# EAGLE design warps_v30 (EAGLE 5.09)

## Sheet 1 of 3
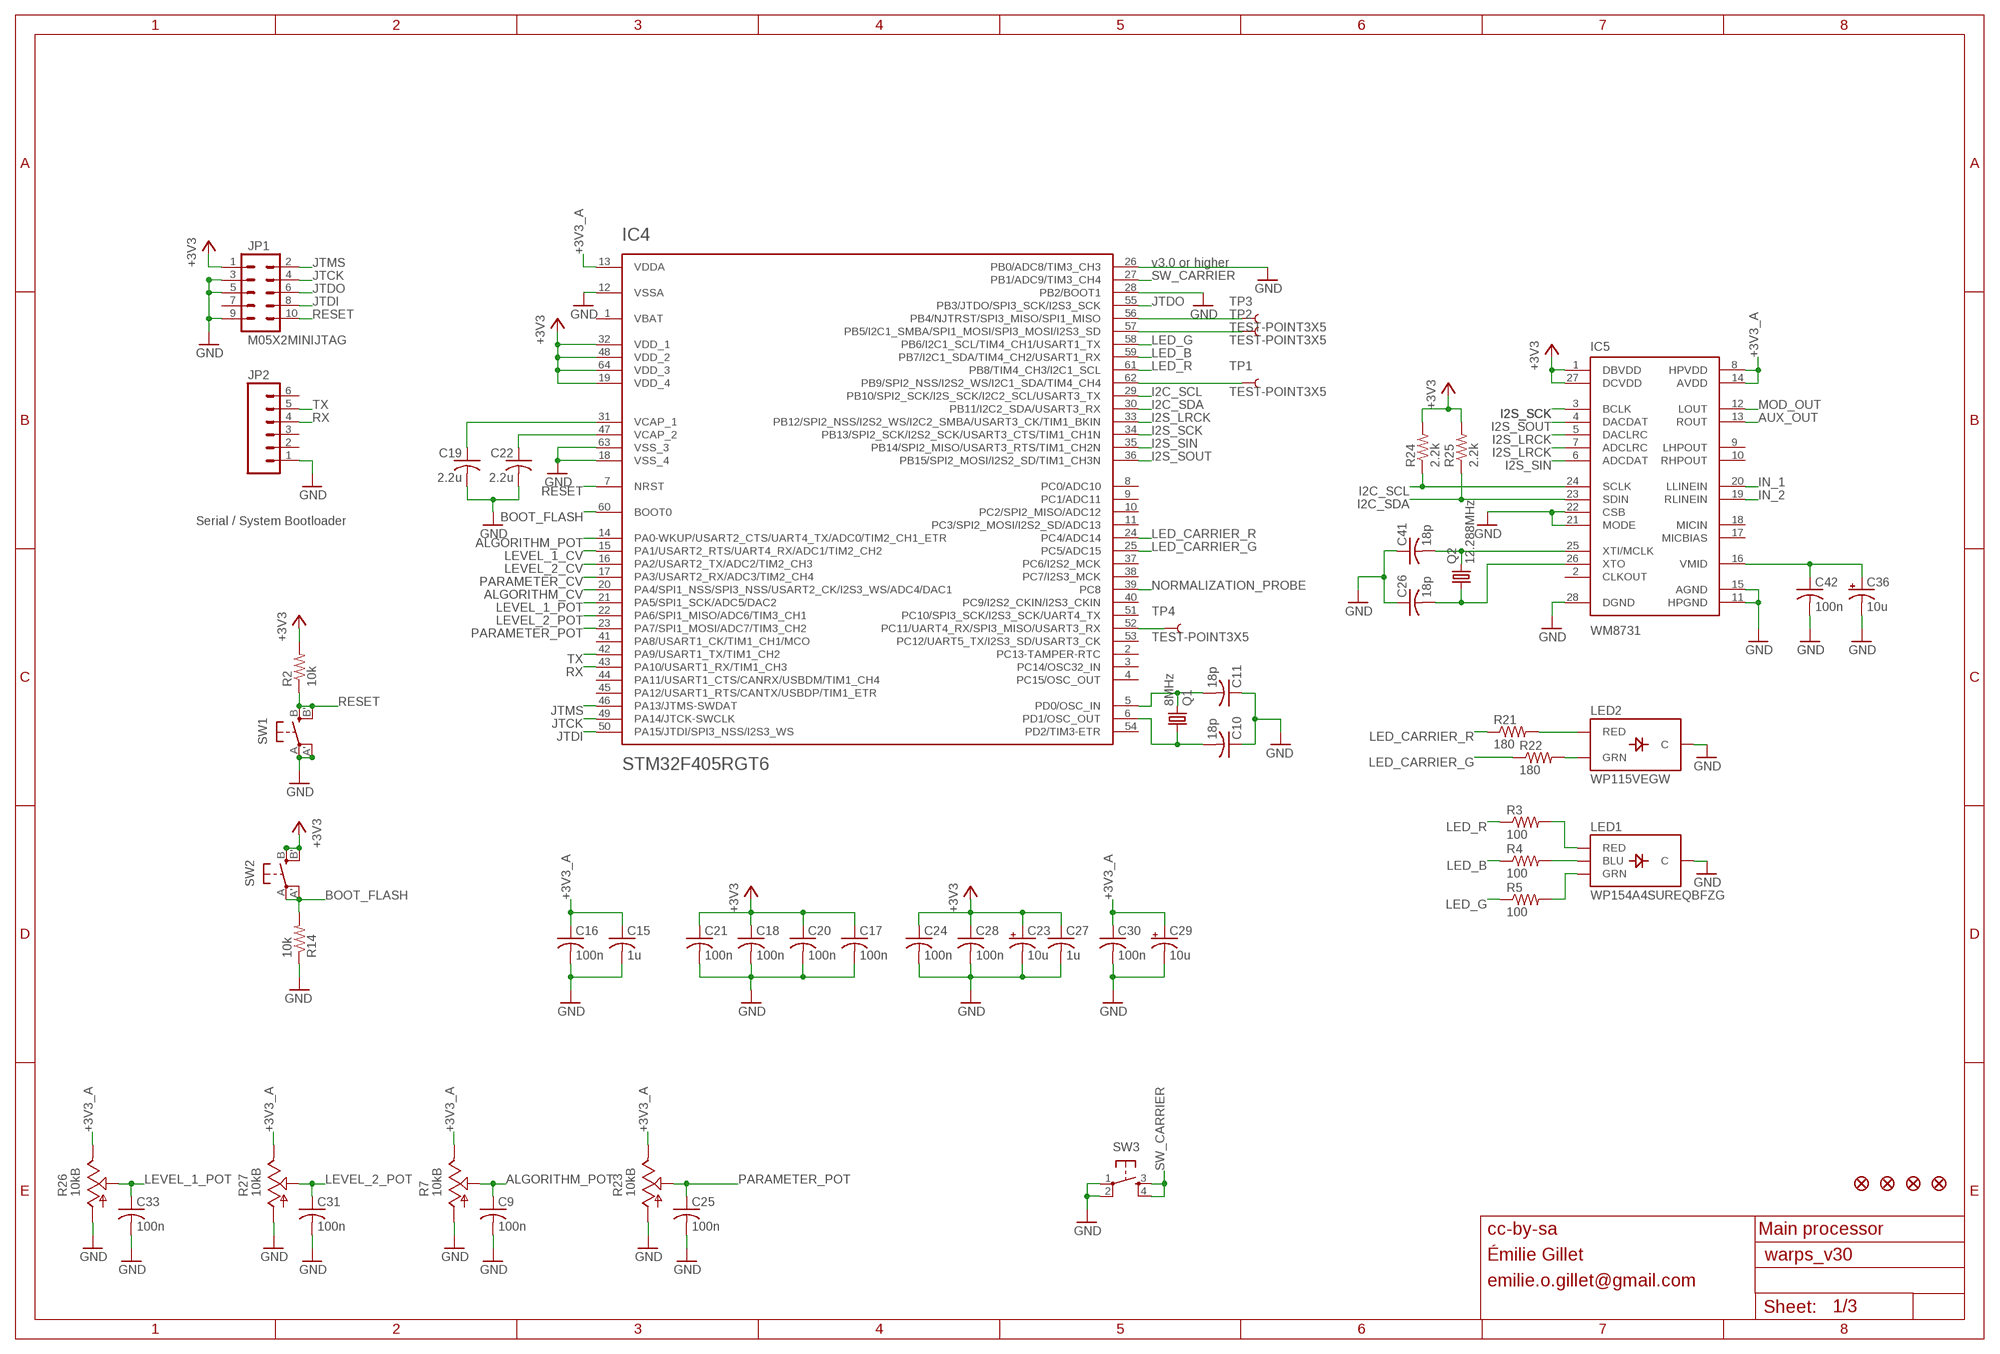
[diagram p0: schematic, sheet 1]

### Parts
C9  100n  C-USC0603  [C0603]
C10  18p  C-USC0603  [C0603]
C11  18p  C-USC0603  [C0603]
C15  1u  C-USC0603  [C0603]
C16  100n  C-USC0603  [C0603]
C17  100n  C-USC0603  [C0603]
C18  100n  C-USC0603  [C0603]
C19  2.2u  C-USC0805  [C0805]
C20  100n  C-USC0603  [C0603]
C21  100n  C-USC0603  [C0603]
C22  2.2u  C-USC0805  [C0805]
C23  10u  CPOL-USA  [PANASONIC_A]
C24  100n  C-USC0603  [C0603]
C25  100n  C-USC0603  [C0603]
C26  18p  C-USC0603  [C0603]
C27  1u  C-USC0603  [C0603]
C28  100n  C-USC0603  [C0603]
C29  10u  CPOL-USA  [PANASONIC_A]
C30  100n  C-USC0603  [C0603]
C31  100n  C-USC0603  [C0603]
C33  100n  C-USC0603  [C0603]
C36  10u  CPOL-USA  [PANASONIC_A]
C41  18p  C-USC0603  [C0603]
C42  100n  C-USC0603  [C0603]
F1  FIDUCIAL1X2  [FIDUCIAL-1X2]
F2  FIDUCIAL1X2  [FIDUCIAL-1X2]
F3  FIDUCIAL1X2  [FIDUCIAL-1X2]
F4  FIDUCIAL1X2  [FIDUCIAL-1X2]
IC4  STM32F405RGT6  STM32F20X  [TQFP-10X10-64]
IC5  WM8731  [SSOP28]
JP1  M05X2MINIJTAG  [2X5-1.27]
JP2  M06SIP  [1X06]
LED1  WP154A4SUREQBFZG  LED-TRICOLOR-THROUGHHOLE  [LED-TRICOLOR-THROUGHHOLE]
LED2  WP115VEGW  LED-BICOLOR-THROUGHHOLE  [LED-BICOLOR-THROUGHHOLE]
Q1  8MHz  CRYSTALHC49UP  [HC49UP]
Q2  12.288MHz  CRYSTALHC49UP  [HC49UP]
R2  10k  R-US_R0603  [R0603]
R3  100  R-US_R0603  [R0603]
R4  100  R-US_R0603  [R0603]
R5  100  R-US_R0603  [R0603]
R7  10kB  POT_USVERTICAL_PS  [ALPS_POT_VERTICAL_PS]
R14  10k  R-US_R0603  [R0603]
R21  180  R-US_R0603  [R0603]
R22  180  R-US_R0603  [R0603]
R23  10kB  POT_USVERTICAL_PS  [ALPS_POT_VERTICAL_PS]
R24  2.2k  R-US_R0603  [R0603]
R25  2.2k  R-US_R0603  [R0603]
R26  10kB  POT_USVERTICAL  [ALPS_POT_VERTICAL]
R27  10kB  POT_USVERTICAL  [ALPS_POT_VERTICAL]
SW1  EVQQ2  [EVQ-Q2]
SW2  EVQQ2  [EVQ-Q2]
SW3  TAC_SWITCHPTH  [TACTILE-PTH]
TP1  TEST-POINT3X5  [PAD.03X.05]
TP2  TEST-POINT3X5  [PAD.03X.05]
TP3  TEST-POINT3X5  [PAD.03X.05]
TP4  TEST-POINT3X5  [PAD.03X.05]

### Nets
+3V3: C17.1 C18.1 C20.1 C21.1 C23.+ C24.1 C27.1 C28.1 IC4.19(VDD_4) IC4.32(VDD_1) IC4.48(VDD_2) IC4.64(VDD_3) IC5.1(DBVDD) IC5.27(DCVDD) JP1.1 R2.2 R24.2 R25.2 SW2.B'(S1) SW2.B(S) ; also sheet 2,3
+3V3_A: C15.1 C16.1 C29.+ C30.1 IC4.13(VDDA) IC5.8(HPVDD) IC5.14(AVDD) R7.P$1(E) R23.P$1(E) R26.P$1(E) R27.P$1(E) ; also sheet 2,3
ALGORITHM_CV: IC4.20(PA4/SPI1_NSS/SPI3_NSS/USART2_CK/I2S3_WS/ADC4/DAC1) ; also sheet 2
ALGORITHM_POT: C9.1 IC4.14(PA0-WKUP/USART2_CTS/UART4_TX/ADC0/TIM2_CH1_ETR) R7.P$2(S)
AUX_OUT: IC5.13(ROUT) ; also sheet 2
BOOT_FLASH: IC4.60(BOOT0) R14.2 SW2.A'(P1) SW2.A(P)
GND: C9.2 C10.1 C11.1 C15.2 C16.2 C17.2 C18.2 C19.2 C20.2 C21.2 C22.2 C23.- C24.2 C25.2 C26.1 C27.2 C28.2 C29.- C30.2 C31.2 C33.2 C36.- C41.1 C42.2 IC4.12(VSSA) IC4.18(VSS_4) IC4.26(PB0/ADC8/TIM3_CH3) IC4.28(PB2/BOOT1) IC4.63(VSS_3) IC5.11(HPGND) IC5.15(AGND) IC5.21(MODE) IC5.22(CSB) IC5.28(DGND) JP1.3 JP1.5 JP1.9 JP2.1 LED1.GND(C) LED2.2(C) R7.P$3(A) R14.1 R23.P$3(A) R26.P$3(A) R27.P$3(A) SW1.A'(P1) SW1.A(P) SW3.1 SW3.2 ; also sheet 2,3
I2C_SCL: IC4.29(PB10/SPI2_SCK/I2S_SCK/I2C2_SCL/USART3_TX) IC5.24(SCLK) R24.1
I2C_SDA: IC4.30(PB11/I2C2_SDA/USART3_RX) IC5.23(SDIN) R25.1
I2S_LRCK: IC4.33(PB12/SPI2_NSS/I2S2_WS/I2C2_SMBA/USART3_CK/TIM1_BKIN) IC5.5(DACLRC) IC5.7(ADCLRC)
I2S_SCK: IC4.34(PB13/SPI2_SCK/I2S2_SCK/USART3_CTS/TIM1_CH1N) IC5.3(BCLK)
I2S_SIN: IC4.35(PB14/SPI2_MISO/USART3_RTS/TIM1_CH2N) IC5.6(ADCDAT)
I2S_SOUT: IC4.36(PB15/SPI2_MOSI/I2S2_SD/TIM1_CH3N) IC5.4(DACDAT)
IN_1: IC5.20(LLINEIN) ; also sheet 2
IN_2: IC5.19(RLINEIN) ; also sheet 2
JTCK: IC4.49(PA14/JTCK-SWCLK) JP1.4
JTDI: IC4.50(PA15/JTDI/SPI3_NSS/I2S3_WS) JP1.8
JTDO: IC4.55(PB3/JTDO/SPI3_SCK/I2S3_SCK) JP1.6
JTMS: IC4.46(PA13/JTMS-SWDAT) JP1.2
LED_B: IC4.59(PB7/I2C1_SDA/TIM4_CH2/USART1_RX) R4.1
LED_CARRIER_G: IC4.25(PC5/ADC15) R22.1
LED_CARRIER_R: IC4.24(PC4/ADC14) R21.1
LED_G: IC4.58(PB6/I2C1_SCL/TIM4_CH1/USART1_TX) R5.1
LED_R: IC4.61(PB8/TIM4_CH3/I2C1_SCL) R3.1
LEVEL_1_CV: IC4.15(PA1/USART2_RTS/UART4_RX/ADC1/TIM2_CH2) ; also sheet 2
LEVEL_1_POT: C33.1 IC4.21(PA5/SPI1_SCK/ADC5/DAC2) R26.P$2(S)
LEVEL_2_CV: IC4.16(PA2/USART2_TX/ADC2/TIM2_CH3) ; also sheet 2
LEVEL_2_POT: C31.1 IC4.22(PA6/SPI1_MISO/ADC6/TIM3_CH1) R27.P$2(S)
MOD_OUT: IC5.12(LOUT) ; also sheet 2
N$3: LED2.3(RED) R21.2
N$7: C11.2 IC4.5(PD0/OSC_IN) Q1.2
N$8: C10.2 IC4.6(PD1/OSC_OUT) Q1.1
N$13: C22.1 IC4.47(VCAP_2)
N$14: LED2.1(GRN) R22.2
N$17: C36.+ C42.1 IC5.16(VMID)
N$19: C19.1 IC4.31(VCAP_1)
N$24: IC4.56(PB4/NJTRST/SPI3_MISO/SPI1_MISO) TP3.P$1
N$26: IC4.57(PB5/I2C1_SMBA/SPI1_MOSI/SPI3_MOSI/I2S3_SD) TP2.P$1
N$27: IC4.52(PC11/UART4_RX/SPI3_MISO/USART3_RX) TP4.P$1
N$30: IC4.62(PB9/SPI2_NSS/I2S2_WS/I2C1_SDA/TIM4_CH4) TP1.P$1
N$35: LED1.RED R3.2
N$36: LED1.BLU R4.2
N$37: LED1.GRN R5.2
N$40: C41.2 IC5.25(XTI/MCLK) Q2.2
N$41: C26.2 IC5.26(XTO) Q2.1
NORMALIZATION_PROBE: IC4.39(PC8) ; also sheet 2
PARAMETER_CV: IC4.17(PA3/USART2_RX/ADC3/TIM2_CH4) ; also sheet 2
PARAMETER_POT: C25.1 IC4.23(PA7/SPI1_MOSI/ADC7/TIM3_CH2) R23.P$2(S)
RESET: IC4.7(NRST) JP1.10 R2.1 SW1.B'(S1) SW1.B(S)
RX: IC4.43(PA10/USART1_RX/TIM1_CH3) JP2.4
SW_CARRIER: IC4.27(PB1/ADC9/TIM3_CH4) SW3.3 SW3.4
TX: IC4.42(PA9/USART1_TX/TIM1_CH2) JP2.5
Unconnected: IC4.2(PC13-TAMPER-RTC) IC4.3(PC14/OSC32_IN) IC4.4(PC15/OSC_OUT) IC4.8(PC0/ADC10) IC4.9(PC1/ADC11) IC4.10(PC2/SPI2_MISO/ADC12) IC4.11(PC3/SPI2_MOSI/I2S2_SD/ADC13) IC4.37(PC6/I2S2_MCK) IC4.38(PC7/I2S3_MCK) IC4.40(PC9/I2S2_CKIN/I2S3_CKIN) IC4.41(PA8/USART1_CK/TIM1_CH1/MCO) IC4.44(PA11/USART1_CTS/CANRX/USBDM/TIM1_CH4) IC4.45(PA12/USART1_RTS/CANTX/USBDP/TIM1_ETR) IC4.51(PC10/SPI3_SCK/I2S3_SCK/UART4_TX) IC4.53(PC12/UART5_TX/I2S3_SD/USART3_CK) IC4.54(PD2/TIM3-ETR) IC5.2(CLKOUT) IC5.9(LHPOUT) IC5.10(RHPOUT) IC5.17(MICBIAS) IC5.18(MICIN) JP1.7 JP2.2 JP2.3 JP2.6

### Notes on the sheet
- v3.0 or higher
- Serial / System Bootloader
- cc-by-sa | Main processor
- Émilie Gillet
- emilie.o.gillet@gmail.com

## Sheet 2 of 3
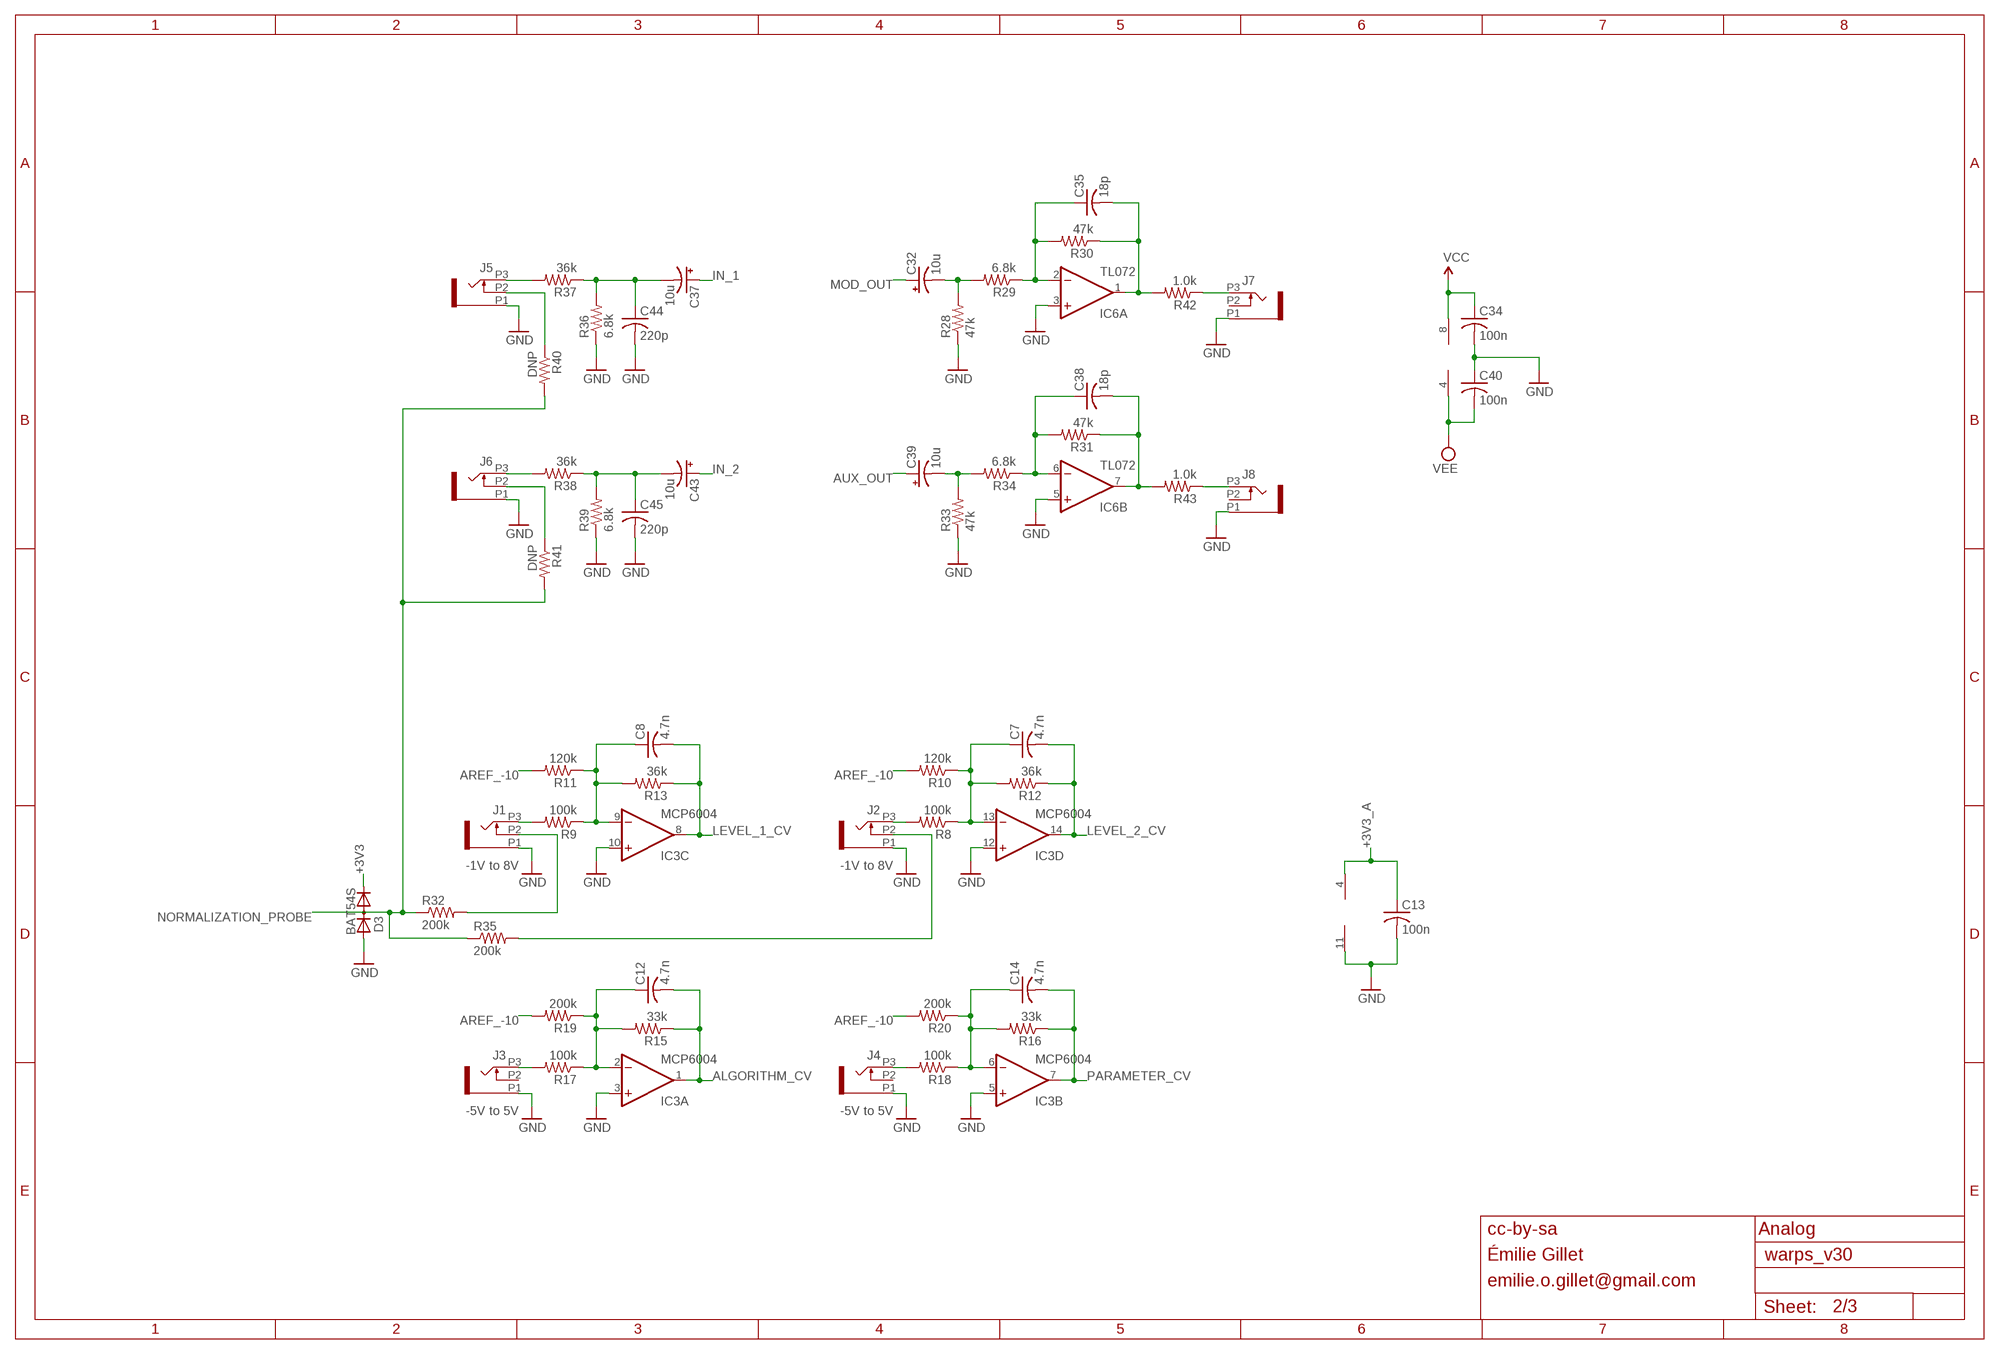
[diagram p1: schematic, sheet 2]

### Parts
C7  4.7n  C-USC0603  [C0603]
C8  4.7n  C-USC0603  [C0603]
C12  4.7n  C-USC0603  [C0603]
C13  100n  C-USC0603  [C0603]
C14  4.7n  C-USC0603  [C0603]
C32  10u  CPOL-USA  [PANASONIC_A]
C34  100n  C-USC0603  [C0603]
C35  18p  C-USC0603  [C0603]
C37  10u  CPOL-USA  [PANASONIC_A]
C38  18p  C-USC0603  [C0603]
C39  10u  CPOL-USA  [PANASONIC_A]
C40  100n  C-USC0603  [C0603]
C43  10u  CPOL-USA  [PANASONIC_A]
C44  220p  C-USC0603  [C0603]
C45  220p  C-USC0603  [C0603]
D3  BAT54S  DIODE_2CACA-SOT23  [SOT23]
IC3  MCP6004  TL074D  [SO14]
IC6  TL072  TL072D  [SO08]
J1  PJ301_THONKICONN6  [WQP_PJ_301M6]
J2  PJ301_THONKICONN6  [WQP_PJ_301M6]
J3  PJ301_THONKICONN6  [WQP_PJ_301M6]
J4  PJ301_THONKICONN6  [WQP_PJ_301M6]
J5  PJ301_THONKICONN6  [WQP_PJ_301M6]
J6  PJ301_THONKICONN6  [WQP_PJ_301M6]
J7  PJ301_THONKICONN6  [WQP_PJ_301M6]
J8  PJ301_THONKICONN6  [WQP_PJ_301M6]
R8  100k  R-US_R0603  [R0603]
R9  100k  R-US_R0603  [R0603]
R10  120k  R-US_R0603  [R0603]
R11  120k  R-US_R0603  [R0603]
R12  36k  R-US_R0603  [R0603]
R13  36k  R-US_R0603  [R0603]
R15  33k  R-US_R0603  [R0603]
R16  33k  R-US_R0603  [R0603]
R17  100k  R-US_R0603  [R0603]
R18  100k  R-US_R0603  [R0603]
R19  200k  R-US_R0603  [R0603]
R20  200k  R-US_R0603  [R0603]
R28  47k  R-US_R0603  [R0603]
R29  6.8k  R-US_R0603  [R0603]
R30  47k  R-US_R0603  [R0603]
R31  47k  R-US_R0603  [R0603]
R32  200k  R-US_R0603  [R0603]
R33  47k  R-US_R0603  [R0603]
R34  6.8k  R-US_R0603  [R0603]
R35  200k  R-US_R0603  [R0603]
R36  6.8k  R-US_R0603  [R0603]
R37  36k  R-US_R0603  [R0603]
R38  36k  R-US_R0603  [R0603]
R39  6.8k  R-US_R0603  [R0603]
R40  DNP  R-US_R0603  [R0603]
R41  DNP  R-US_R0603  [R0603]
R42  1.0k  R-US_R0603  [R0603]
R43  1.0k  R-US_R0603  [R0603]

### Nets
+3V3: D3.2(C) ; also sheet 1,3
+3V3_A: C13.1 IC3.4(P:V+) ; also sheet 1,3
ALGORITHM_CV: C12.2 IC3.1(A:OUT) R15.1 ; also sheet 1
AREF_-10: R10.2 R11.2 R19.2 R20.2 ; also sheet 3
AUX_OUT: C39.+ ; also sheet 1
GND: C13.2 C34.2 C40.1 C44.2 C45.2 D3.1(A) IC3.3(A:+IN) IC3.5(B:+IN) IC3.10(C:+IN) IC3.11(P:V-) IC3.12(D:+IN) IC6.3(A:+IN) IC6.5(B:+IN) J1.P1 J2.P1 J3.P1 J4.P1 J5.P1 J6.P1 J7.P1 J8.P1 R28.1 R33.1 R36.1 R39.1 ; also sheet 1,3
IN_1: C37.+ ; also sheet 1
IN_2: C43.+ ; also sheet 1
LEVEL_1_CV: C8.2 IC3.8(C:OUT) R13.1 ; also sheet 1
LEVEL_2_CV: C7.2 IC3.14(D:OUT) R12.1 ; also sheet 1
MOD_OUT: C32.+ ; also sheet 1
N$1: J1.P3 R9.2
N$2: C8.1 IC3.9(C:-IN) R9.1 R11.1 R13.2
N$4: J2.P3 R8.2
N$5: C7.1 IC3.13(D:-IN) R8.1 R10.1 R12.2
N$6: J4.P3 R18.2
N$9: J1.P2 R32.2
N$10: J3.P3 R17.2
N$11: C12.1 IC3.2(A:-IN) R15.2 R17.1 R19.1
N$12: J2.P2 R35.2
N$15: C14.1 IC3.6(B:-IN) R16.2 R18.1 R20.1
N$18: C37.- C44.1 R36.2 R37.1
N$20: J6.P3 R38.2
N$21: J5.P3 R37.2
N$22: C43.- C45.1 R38.1 R39.2
N$23: C39.- R33.2 R34.2
N$25: C38.1 IC6.6(B:-IN) R31.2 R34.1
N$28: C38.2 IC6.7(B:OUT) R31.1 R43.2
N$29: J8.P3 R43.1
N$31: C32.- R28.2 R29.2
N$32: C35.1 IC6.2(A:-IN) R29.1 R30.2
N$33: C35.2 IC6.1(A:OUT) R30.1 R42.2
N$34: J7.P3 R42.1
N$38: J6.P2 R41.1
N$39: J5.P2 R40.1
NORMALIZATION_PROBE: D3.3(AC) R32.1 R35.1 R40.2 R41.2 ; also sheet 1
PARAMETER_CV: C14.2 IC3.7(B:OUT) R16.1 ; also sheet 1
VCC: C34.1 IC6.8(P:V+) ; also sheet 3
VEE: C40.2 IC6.4(P:V-) ; also sheet 3
Unconnected: J3.P2 J4.P2 J7.P2 J8.P2

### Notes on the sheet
- -1V to 8V | -1V to 8V
- -5V to 5V | -5V to 5V
- cc-by-sa | Analog
- Émilie Gillet
- emilie.o.gillet@gmail.com

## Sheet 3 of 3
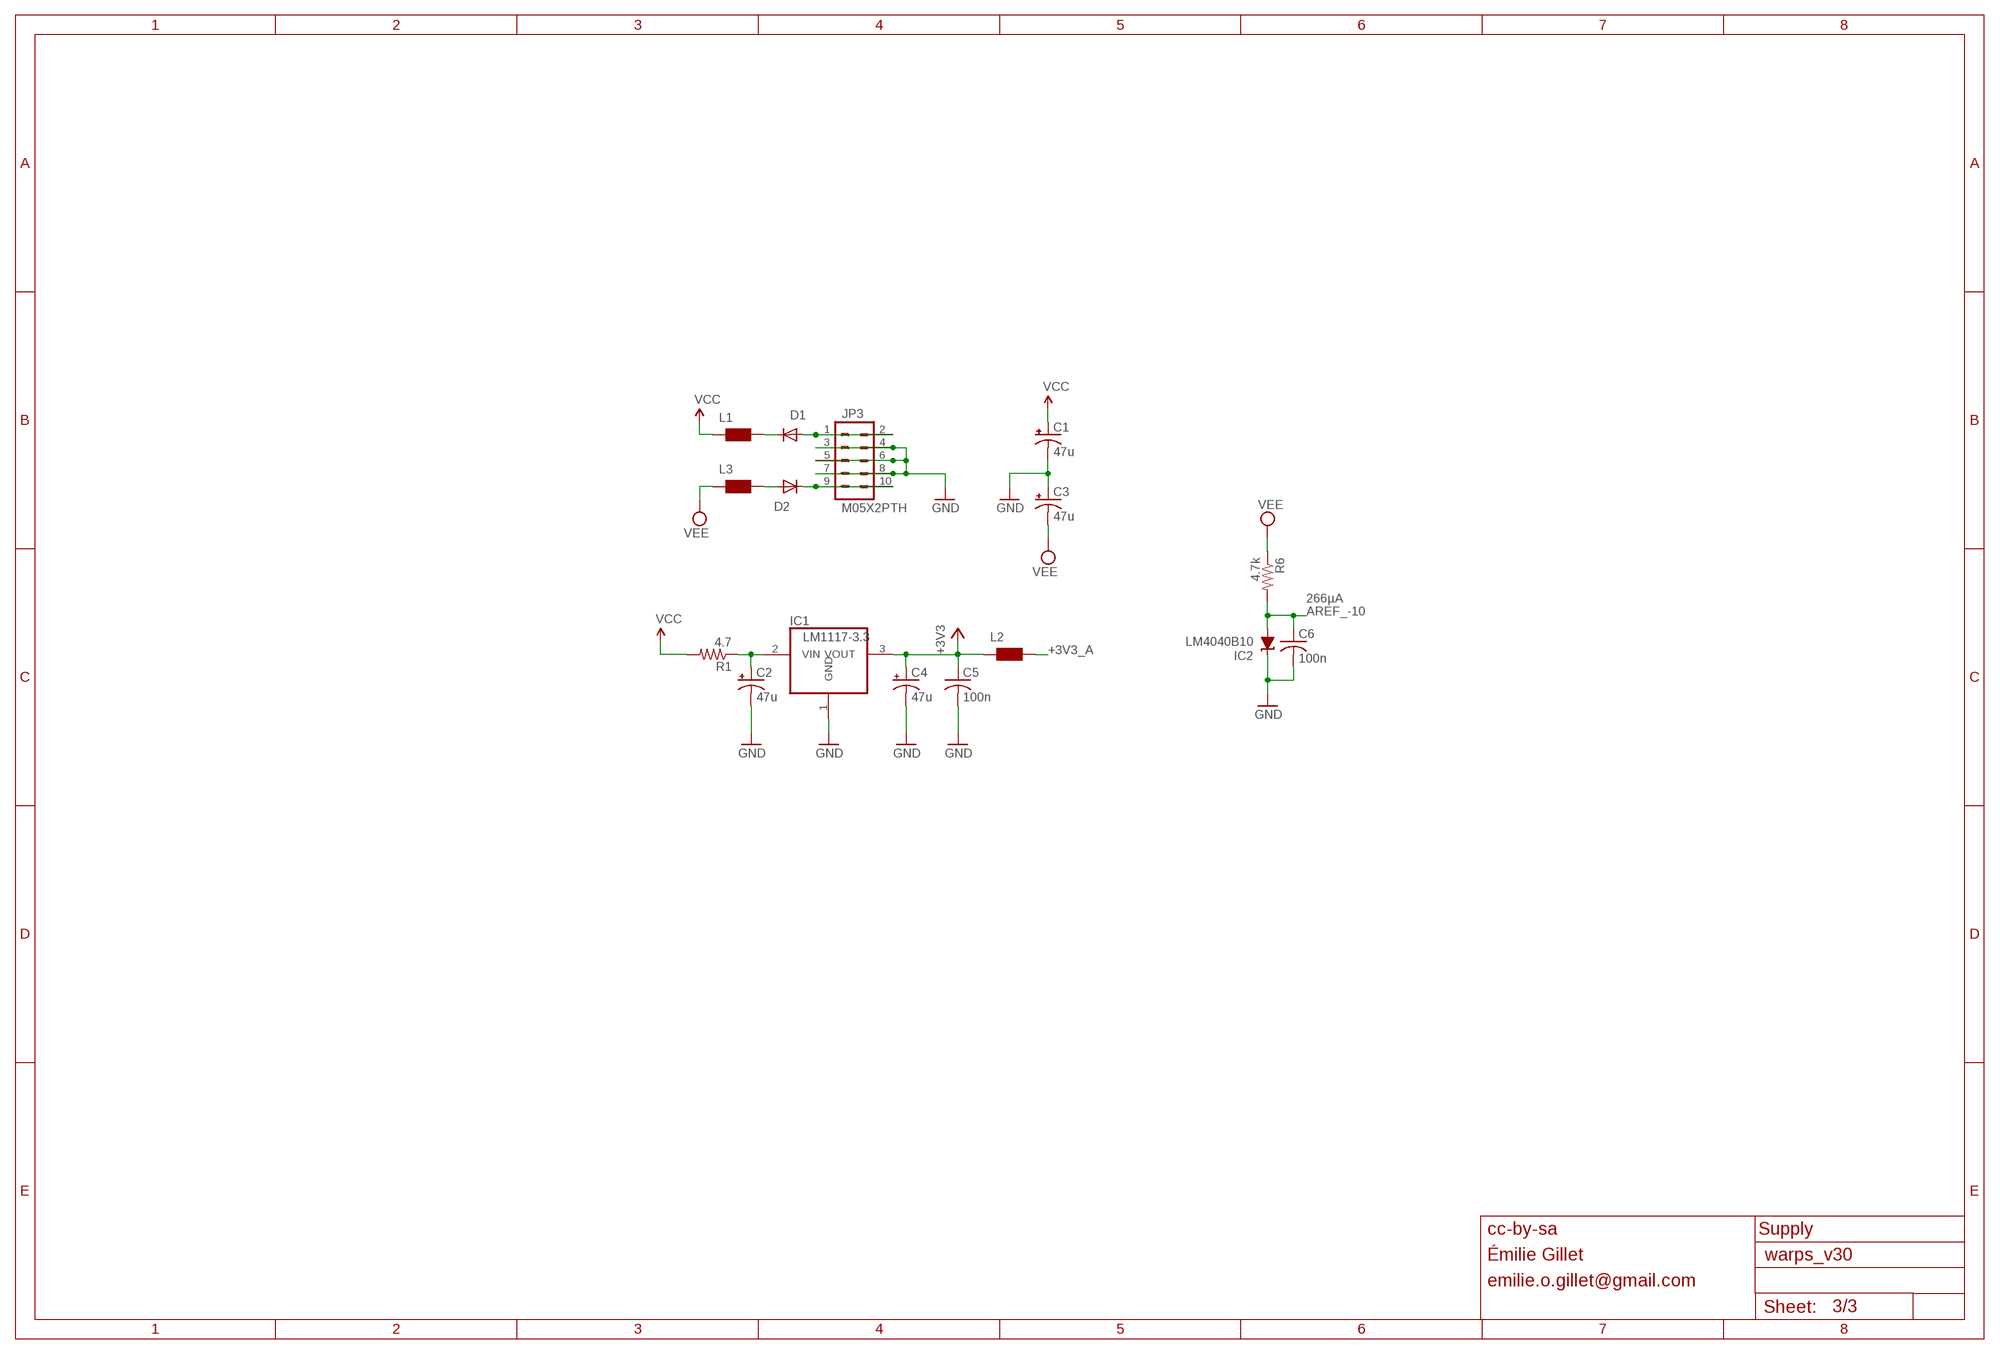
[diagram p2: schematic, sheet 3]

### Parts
C1  47u  CPOL-USD  [PANASONIC_D]
C2  47u  CPOL-USD  [PANASONIC_D]
C3  47u  CPOL-USD  [PANASONIC_D]
C4  47u  CPOL-USD  [PANASONIC_D]
C5  100n  C-USC0603  [C0603]
C6  100n  C-USC0603  [C0603]
D1  1N5819HW  DIODE-SOD123  [SOD123]
D2  1N5819HW  DIODE-SOD123  [SOD123]
IC1  LM1117-3.3  REG1117T  [TO252]
IC2  LM4040B10  LM4041B12DBZ  [DBZ_R-PDSO-G3]
JP3  M05X2PTH  [AVR_ICSP]
L1  WE-CBF_0603  [0603]
L2  WE-CBF_0603  [0603]
L3  WE-CBF_0603  [0603]
R1  4.7  R-US_R1206  [R1206]
R6  4.7k  R-US_R0603  [R0603]

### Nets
+3V3: C4.+ C5.1 IC1.3(VOUT) L2.1 ; also sheet 1,2
+3V3_A: L2.2 ; also sheet 1,2
AREF_-10: C6.1 IC2.2(A) R6.2 ; also sheet 2
GND: C1.- C2.- C3.+ C4.- C5.2 C6.2 IC1.1(GND) IC2.1(C) JP3.3 JP3.4 JP3.5 JP3.6 JP3.7 JP3.8 ; also sheet 1,2
N$16: C2.+ IC1.2(VIN) R1.1
N$42: D1.C L1.2
N$43: D2.A L3.2
N$56: D1.A JP3.1 JP3.2
N$64: D2.C JP3.9 JP3.10
VCC: C1.+ L1.1 R1.2 ; also sheet 2
VEE: C3.- L3.1 R6.1 ; also sheet 2

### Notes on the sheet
- 266µA
- cc-by-sa | Supply
- Émilie Gillet
- emilie.o.gillet@gmail.com

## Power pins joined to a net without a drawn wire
VBAT: IC4.1(VBAT)

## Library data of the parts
C1-C4 C23 C29 C32 C36 C37 C39 C43 = rcl:CPOL-US: POLARIZED CAPACITOR, American symbol
C5-C22 C24-C28 C30 C31 C33-C35 C38 C40-C42 C44 C45 = rcl:C-US: CAPACITOR, American symbol
D1 D2 = diode:DIODE-: DIODE
D3 = diode:DIODE_2CACA-: 2 Diodes - Cathode-Anode|Cathode-Anode
F1-F4 = SparkFun:FIDUCIAL: Fiducial Alignment Points
IC1 = og-vreg:REG1117: 800mA and 1A Low Dropout (LDO) Positive Regulator 1.8V, 2.5V, 2.85V, 3.3V, 5V, and Adj
IC2 = texas:LM4041: PRECISION MICROPOWER SHUNT VOLTAGE REFERENCE
IC3 = gm-ics:TL074: OP AMP
IC4 = og-stm32f2:STM32F20X
IC5 = og-dac:WM8731
IC6 = og-linear:TL072: OP AMP
J1-J8 = og-pj301:PJ301_THONKICONN
JP1 JP3 = og-header:M05X2: Header 5x2 Standard 10-pin dual row 0.1" header. Commonly used with AVR-ISP. Use with Spark Fun Electronics SKU: PRT-00778
JP2 = SparkFun:M06: Header 6 Standard 6-pin 0.1" header. Use with straight break away headers (SKU : PRT-00116), right angle break away headers (PRT-00553), swiss pins (PRT-00743), machine pins (PRT-00117), and female headers (PRT-00115). Molex polarized connector foot print use with SKU : PRT-08094 with associated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
L1-L3 = wuerth-elektronik:WE-CBF: SMD EMI Suppression Ferrite Beads
LED1 = og-leds:LED-TRICOLOR-THROUGHHOLE
LED2 = og-leds:LED-BICOLOR-THROUGHHOLE
Q1 Q2 = crystal:CRYSTAL: CRYSTAL
R1-R6 R8-R22 R24 R25 R28-R43 = rcl:R-US_: RESISTOR, American symbol
R7 R23 R26 R27 = og-pots:POT_US
SW1 SW2 = adafruit:EVQQ2: SMT 6mm switch, EVQQ2 series http://www.ladyada.net/library/eagle
SW3 = SparkFun:TAC_SWITCH: Momentary Switch Button commonly used for reset or general input. Spark Fun Electronics SKU : COM-00097
TP1-TP4 = SparkFun:TEST-POINT

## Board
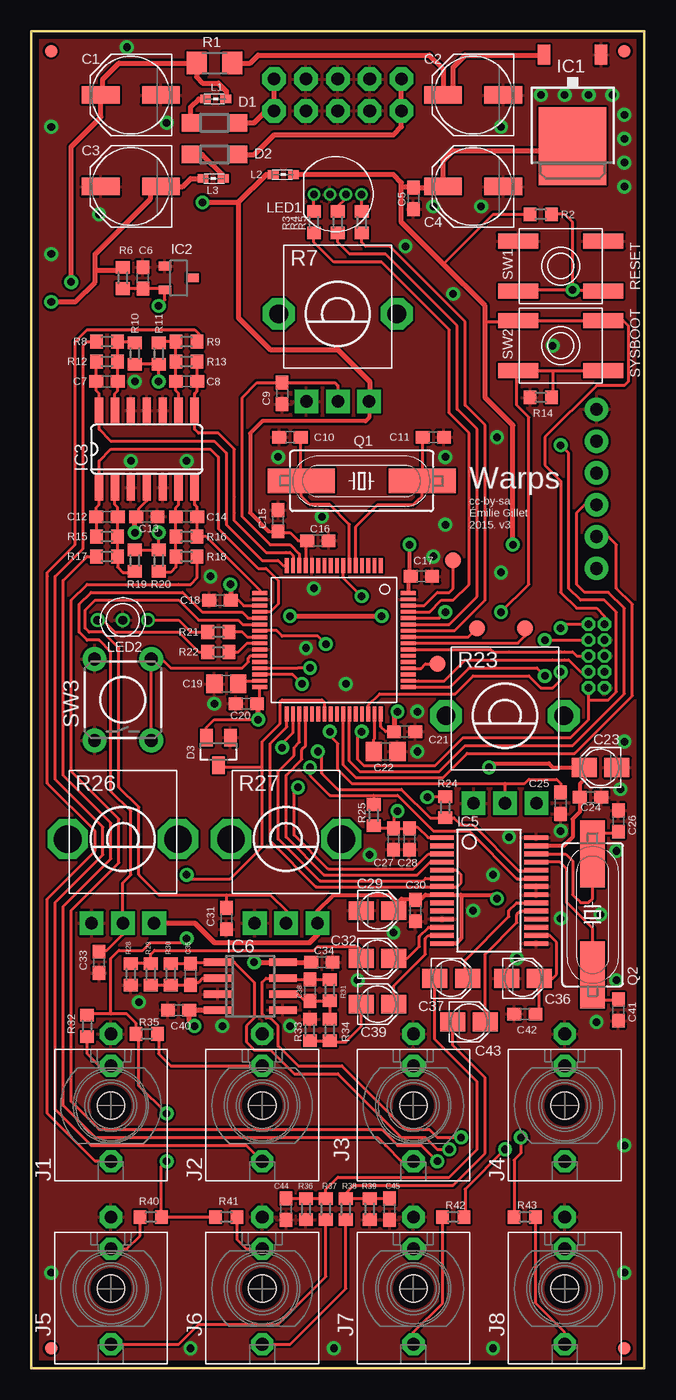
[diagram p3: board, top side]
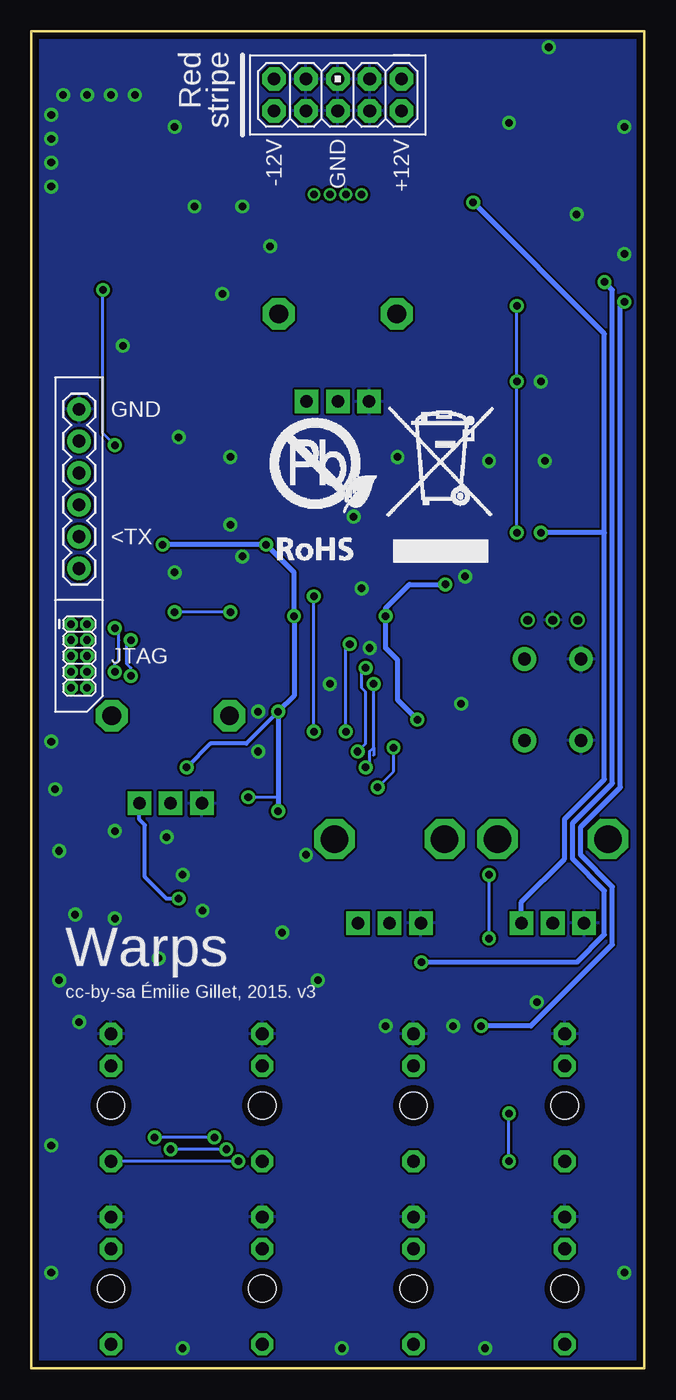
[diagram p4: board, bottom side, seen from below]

Size 48.9 x 106.68 mm. Coordinates in mm from the lower left corner, seen from the top.
Outline: 0,0 48.9,0 48.9,106.68 0,106.68 0,0
Copper layers (1*16): Top 0.035mm / dielectric 1.5mm / Bottom 0.035mm
Design rules "PCBCart-Standard-Fine": minimum track width 8mil, minimum drill 0.4mm, track to track 7mil, track to pad 7mil, pad to pad 7mil, via to via 7mil, smd to smd 7mil, copper to edge 20mil, drill to drill 8mil, minimum pad ring 8mil, minimum via ring 10mil, stop-mask expansion 3mil, vias tented up to drill 25mil, thermal gap 8mil

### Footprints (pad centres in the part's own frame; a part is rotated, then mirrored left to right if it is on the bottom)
PANASONIC_D = smd 3 x 1.4: + 2.4,0; - -2.4,0
C0603 = smd 1.1 x 1: 1 -0.85,0; 2 0.85,0
C0805 = smd 1.3 x 1.5: 1 -0.95,0; 2 0.95,0
PANASONIC_A = smd 2 x 1.5: + 1.3,0; - -1.3,0
SOD123 = smd 1.4 x 1.4: A 1.9,0; C -1.9,0
SOT23 = smd 1 x 1.4: 1 -0.95,-1.1; 2 0.95,-1.1; 3 0,1.1
FIDUCIAL-1X2 = smd 1 x 1: 1 0,0
TO252 = smd 1 x 1.6: 1 -2.28,-4.8; 2 2.28,-4.8 | smd 5.4 x 6.2: 3 0,2.5
DBZ_R-PDSO-G3 = smd 0.7 x 1: 1 -0.95,-1.1; 2 0.95,-1.1; 3 0,1.1
SO14 = smd 0.66 x 2.032: 1 -3.81,-3.073; 2 -2.54,-3.073; 3 -1.27,-3.073; 4 0,-3.073; 5 1.27,-3.073; 6 2.54,-3.073; 7 3.81,-3.073; 8 3.81,3.073; 9 2.54,3.073; 10 1.27,3.073; 11 0,3.073; 12 -1.27,3.073; 13 -2.54,3.073; 14 -3.81,3.073
TQFP-10X10-64 = smd 1.2 x 0.3: 1 -5.936,3.75; 2 -5.936,3.25; 3 -5.936,2.75; 4 -5.936,2.25; 5 -5.936,1.75; 6 -5.936,1.25; 7 -5.936,0.75; 8 -5.936,0.25; 9 -5.936,-0.25; 10 -5.936,-0.75; 11 -5.936,-1.25; 12 -5.936,-1.75; 13 -5.936,-2.25; 14 -5.936,-2.75; 15 -5.936,-3.25; 16 -5.936,-3.75; 33 5.886,-3.75; 34 5.886,-3.25; 35 5.886,-2.75; 36 5.886,-2.25; 37 5.886,-1.75; 38 5.886,-1.25; 39 5.886,-0.75; 40 5.886,-0.25; 41 5.886,0.25; 42 5.886,0.75; 43 5.886,1.25; 44 5.886,1.75; 45 5.886,2.25; 46 5.886,2.75; 47 5.886,3.25; 48 5.886,3.75 | smd 0.3 x 1.2: 17 -3.75,-5.911; 18 -3.25,-5.911; 19 -2.75,-5.911; 20 -2.25,-5.911; 21 -1.75,-5.911; 22 -1.25,-5.911; 23 -0.75,-5.911; 24 -0.25,-5.911; 25 0.25,-5.911; 26 0.75,-5.911; 27 1.25,-5.911; 28 1.75,-5.911; 29 2.25,-5.911; 30 2.75,-5.911; 31 3.25,-5.911; 32 3.75,-5.911; 49 3.75,5.936; 50 3.25,5.936; 51 2.75,5.936; 52 2.25,5.936; 53 1.75,5.936; 54 1.25,5.936; 55 0.75,5.936; 56 0.25,5.936; 57 -0.25,5.936; 58 -0.75,5.936; 59 -1.25,5.936; 60 -1.75,5.936; 61 -2.25,5.936; 62 -2.75,5.936; 63 -3.25,5.936; 64 -3.75,5.936
SSOP28 = smd 0.381 x 1.905: 1 -4.55,-3.752; 2 -3.9,-3.752; 3 -3.25,-3.752; 4 -2.6,-3.752; 5 -1.95,-3.752; 6 -1.3,-3.752; 7 -0.65,-3.752; 8 0,-3.752; 9 0.65,-3.752; 10 1.3,-3.752; 11 1.95,-3.752; 12 2.6,-3.752; 13 3.25,-3.752; 14 3.9,-3.752; 15 3.9,3.752; 16 3.25,3.752; 17 2.6,3.752; 18 1.95,3.752; 19 1.3,3.752; 20 0.65,3.752; 21 0,3.752; 22 -0.65,3.752; 23 -1.3,3.752; 24 -1.95,3.752; 25 -2.6,3.752; 26 -3.25,3.752; 27 -3.9,3.752; 28 -4.55,3.752
SO08 = smd 0.6 x 2.2: 1 -1.905,-2.6; 2 -0.635,-2.6; 3 0.635,-2.6; 4 1.905,-2.6; 5 1.905,2.6; 6 0.635,2.6; 7 -0.635,2.6; 8 -1.905,2.6
WQP_PJ_301M6 = drill 1.016 pad 1.778 octagon: P1 0,-5.715; P2 0,-3.175; P3 0,4.445 | hole 2.2: 0,0
2X5-1.27 = drill 0.61 pad 1.067 octagon: 1 -1.27,3.81; 2 0,3.81; 3 -1.27,2.54; 4 0,2.54; 5 -1.27,1.27; 6 0,1.27; 7 -1.27,0; 8 0,0; 9 -1.27,-1.27; 10 0,-1.27
1X06 = drill 1.016 pad 1.88 round: 1 0,0; 2 2.54,0; 3 5.08,0; 4 7.62,0; 5 10.16,0; 6 12.7,0
AVR_ICSP = drill 1.016 pad 1.88 octagon: 1 -1.27,5.08; 2 1.27,5.08; 3 -1.27,2.54; 4 1.27,2.54; 5 -1.27,0; 6 1.27,0; 7 -1.27,-2.54; 8 1.27,-2.54; 9 -1.27,-5.08; 10 1.27,-5.08
0603 = smd 0.85 x 0.7: 1 -0.9,0; 2 0.7,0
LED-TRICOLOR-THROUGHHOLE = drill 0.6 round: BLU 0.635,0; GND -0.635,0; GRN 1.905,0; RED -1.905,0
LED-BICOLOR-THROUGHHOLE = drill 0.7 round: 1 -2,0; 2 0,0; 3 2,0
HC49UP = smd 5.334 x 1.93: 1 -4.826,0; 2 4.826,0
R1206 = smd 1.6 x 1.803: 1 -1.422,0; 2 1.422,0
R0603 = smd 1 x 1.1: 1 -0.85,0; 2 0.85,0
ALPS_POT_VERTICAL_PS = drill 1 pad 1.88 square: P$1 -2.5,7; P$2 0,7; P$3 2.5,7 | drill 1.5 pad 2.54 octagon: P$4 -4.7,0; P$5 4.7,0
ALPS_POT_VERTICAL = drill 1 pad 1.88 square: P$1 -2.5,6.7; P$2 0,6.7; P$3 2.5,6.7 | drill 2.2 pad 3.175 octagon: P$4 -4.4,0; P$5 4.4,0
EVQ-Q2 = smd 3.2 x 1.2: A -3.4,-2; A' 3.4,-2; B -3.4,2; B' 3.4,2
TACTILE-PTH = drill 1.016 pad 1.88 round: 1 -3.251,2.261; 2 3.251,2.261; 3 -3.251,-2.261; 4 3.251,-2.261
PAD.03X.05 = smd 1.27 x 1.27: P$1 0,0

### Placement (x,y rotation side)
C1  7.94,101.6 180 top
C2  35.24,101.6 180 top
C3  7.94,94.3 180 top
C4  35.24,94.3 180 top
C5  30.48,93.34 270 top
C6  8.89,87 90 top
C7  6.03,78.74 180 top
C8  12.38,78.74 0 top
C9  20,77.79 270 top
C10  20.64,74.3 0 top
C11  32.07,74.3 180 top
C12  6.03,67.94 180 top
C13  9.21,67.94 0 top
C14  12.38,67.94 0 top
C15  19.68,67.63 90 top
C16  22.86,66.04 0 top
C17  31.11,63.18 0 top
C18  15.05,61.28 180 top
C19  15.56,54.61 180 top
C20  17.14,53.02 180 top
C21  29.78,50.8 0 top
C22  28.26,49.21 0 top
C23  45.4,47.94 180 top
C24  44.61,45.56 0 top
C25  42.23,45.09 270 top
C26  46.83,43.66 270 top
C27  28.89,42.23 270 top
C28  30.16,42.23 270 top
C29  27.62,36.51 0 top
C30  30.64,36.51 270 top
C31  15.56,35.88 270 top
C32  27.62,32.7 0 top
C33  5.4,32.38 270 top
C34  23.18,32.38 0 top
C35  12.7,31.43 90 top
C36  39.21,31.11 0 top
C37  33.5,31.11 0 top
C38  22.23,30.16 90 top
C39  27.62,29.05 0 top
C40  11.75,28.57 0 top
C41  46.83,28.57 90 top
C42  39.37,28.26 180 top
C43  34.92,27.62 0 top
C44  20.32,12.7 270 top
C45  28.57,12.7 270 top
D1  14.61,99.38 0 top
D2  14.61,96.84 180 top
D3  14.92,49.21 180 top
F1  1.59,105.09 0 top
F2  47.31,105.09 0 top
F3  1.59,1.59 0 top
F4  47.31,1.59 0 top
IC1  43.18,100.01 180 top
IC2  11.75,87 270 top
IC3  9.21,73.34 0 top
IC4  24.13,58.1 270 top
IC5  36.51,37.78 270 top
IC6  17.46,30.48 270 top
J1  6.35,20.95 180 top
J2  18.41,20.95 180 top
J3  30.48,20.95 180 top
J4  42.55,20.95 180 top
J5  6.35,6.35 180 top
J6  18.41,6.35 180 top
J7  30.48,6.35 180 top
J8  42.55,6.35 180 top
JP1  44.45,55.56 0 bottom
JP2  45.09,76.52 270 bottom
JP3  24.45,101.6 270 bottom
L1  14.61,101.28 180 top
L2  20,95.25 180 top
L3  14.61,94.93 0 top
LED1  24.45,93.66 0 top
LED2  7.3,59.69 0 top
Q1  26.35,70.8 0 top
Q2  44.77,36.19 270 top
R1  14.61,104.14 180 top
R2  40.64,92.08 180 top
R3  22.54,91.44 90 top
R4  24.45,91.44 90 top
R5  26.35,91.44 90 top
R6  7.3,87 270 top
R7  24.45,84.14 180 top
R8  6.03,81.92 180 top
R9  12.38,81.92 0 top
R10  8.26,80.96 270 top
R11  10.16,80.96 270 top
R12  6.03,80.33 0 top
R13  12.38,80.33 180 top
R14  40.64,77.47 0 top
R15  6.03,66.36 0 top
R16  12.38,66.36 180 top
R17  6.03,64.77 180 top
R18  12.38,64.77 0 top
R19  8.26,64.45 90 top
R20  10.16,64.45 90 top
R21  14.92,58.74 180 top
R22  14.92,57.15 180 top
R23  37.78,52.07 180 top
R24  33.02,44.77 90 top
R25  27.3,44.13 270 top
R26  7.3,42.23 180 top
R27  20.32,42.23 180 top
R28  7.94,31.43 90 top
R29  9.53,31.43 90 top
R30  11.11,31.43 270 top
R31  23.81,30.16 270 top
R32  4.45,27.3 270 top
R33  22.23,26.99 270 top
R34  23.81,26.99 270 top
R35  9.21,26.67 0 top
R36  21.91,12.7 90 top
R37  23.5,12.7 270 top
R38  25.08,12.7 270 top
R39  26.99,12.7 90 top
R40  9.53,12.06 0 top
R41  15.56,12.06 180 top
R42  33.66,12.06 0 top
R43  39.37,12.06 180 top
SW1  42.23,87.95 180 top
SW2  42.23,81.6 0 top
SW3  7.3,53.34 90 top
TP1  33.66,64.45 0 top
TP2  35.56,59.05 0 top
TP3  39.37,59.05 0 top
TP4  32.38,56.2 0 top
U$2  [ROHS_BIG]  31.11,63.5 0 bottom

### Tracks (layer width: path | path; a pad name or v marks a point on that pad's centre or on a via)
+3V3  (via drill 0.6)
  Top 0.254: C20.1 18.22,53.25 IC4.32 | C21.1 28.26,50.8 27.88,51.18 IC4.48 | JP1.1 45.72,60.01 45.09,60.64 43.5,60.64 42.23,61.91 42.23,70.8 40.96,72.07 40.96,74.3 45.09,78.42 47.31,78.42 47.62,78.74 47.62,83.19 47.21,83.6 SW2.B' SW2.B 38.73,83.5 36.2,83.5 | R2.2 36.83,92.08 32.86,88.11 | C18.1 16.51,61.28 16.93,60.85 IC4.19 | 32.86,88.11 | v29.21,44.45 28.89,44.13 C27.1 | R25.2 27.51,43.08 C27.1 | C27.1 C28.1 30.27,43.18 30.8,43.18 31.64,42.33 IC5.1 | v31.59,45.56 31.65,45.62 R24.2 | D3.2 13.97,51.12 14.61,51.75 v18.1,51.75
  Top 0.305: v30.16,65.72 30.16,63.28 C17.1 30.07,62.98 IC4.64 | v36.51,47.94 36.83,48.26 41.27,48.26 41.59,47.94 C23.+ 44.13,47.94 44.13,46.99 43.76,46.62 C24.1 43.76,44.39 43.18,43.81 43.18,42.39 42.48,41.68 IC5.27
  Top 0.406: v29.21,52.39 28.93,52.11 C21.1 | 18.22,53.25 18.1,53.12 v18.1,51.75 | L2.1 28.89,95.25 29.53,94.61 29.53,94.3 | v38.42,65.72 38.42,75.25 36.2,77.47 36.2,83.5 36.2,84.77 32.86,88.11 29.53,91.44 29.53,94.3 | v15.88,62.55 15.9,62.52 C18.1 | v20.64,60.01 v27.94,60.01 | IC1.3 42.82,97.16 33.66,97.16 32.84,96.34 C4.+ 32.74,94.19 C5.1 30.38,94.3 29.53,94.3
  Bottom 0.254: 29.21,45.56 v31.59,45.56
  Bottom 0.305: v36.51,47.94 34.61,49.85 31.75,49.85 v29.21,52.39
  Bottom 0.406: v38.42,65.72 v30.16,65.72 27.94,63.5 v27.94,60.01 27.94,53.66 v29.21,52.39 29.21,45.56 v29.21,44.45 | v18.1,51.75 19.68,53.34 19.68,56.52 20.64,57.47 v20.64,60.01 20.64,60.64 18.73,62.55 v15.88,62.55
+3V3_A  (via drill 0.6)
  Top 0.254: C13.1 8.57,68.16 8.57,68.58 9.21,69.22 IC3.4 | 18.95,66.78 C15.1 19.79,66.67 20.64,66.67 21.27,66.04 C16.1 21.91,65.94 21.91,65.41 21.88,65.38 IC4.13
  Top 0.305: 26.99,77.18 R7.P$1 26.95,75.84 26.67,75.56 18.41,75.56 17.46,74.61 17.46,68.26 18.95,66.78 | 34.29,37.78 IC5.8 31.43,37.78 31.11,37.47 30.74,37.47 C30.1 30.54,37.47 29.53,37.47 28.92,36.86 C29.+ 28.92,37.44 28.57,37.78 24.13,37.78 22.82,36.47 R27.P$1 | v37.15,37.47 36.83,37.78 34.29,37.78 | 34.29,37.78 34.29,34.29 33.88,33.88 IC5.14
  Top 0.406: 26.99,77.18 26.99,78.74 24.45,81.28 19.05,81.28 16.51,83.82 16.51,93.03 | R26.P$1 13.05,35.53 14.61,33.97 22.23,33.97 22.82,34.57 R27.P$1 | v13.65,93.03 16.51,93.03 | C13.1 8.26,67.84 v8.26,66.67 | L2.2 18.73,95.25 16.51,93.03
  Bottom 0.305: v37.15,37.47 38.1,37.47 39.85,39.21 39.85,43.34 40.28,43.77 R23.P$1
  Bottom 0.406: v13.65,93.03 3.17,82.55 3.17,66.67 | 3.17,66.67 3.17,46.99 6.35,43.81 6.35,40.64 9.8,37.19 R26.P$1 | 3.17,66.67 v8.26,66.67
ALGORITHM_CV
  Top 0.254: R15.1 C12.2 5.18,68.68 5.4,68.9 IC3.1 5.4,72.39 6.35,73.34 14.29,73.34 14.92,72.71 14.92,68.9 14.92,67.63 14.92,66.99 18.1,63.82 18.73,63.82 19.68,62.87 19.68,60.96 19.08,60.35 IC4.20 18.25,60.33
ALGORITHM_POT
  Top 0.254: IC4.14 21.38,64.98 20.64,65.72 19.05,65.72 16.83,67.94 16.83,77.47 18,78.64 C9.1 24.23,78.64 24.45,78.42 R7.P$2
AREF_-10  (via drill 0.6)
  Top 0.254: R10.2 R11.2 v10.16,78.74 | v10.16,66.67 R20.2 R19.2 | R6.2 8.26,86.14 C6.1 10.55,86.14 IC2.2 10.65,85.26 v10.16,84.77
  Bottom 0.254: v10.16,66.67 v10.16,78.74 v10.16,84.77
AUX_OUT
  Top 0.254: IC5.13 31.68,34.53 31.43,34.29 31.43,33.02 29.84,31.43 29.69,31.27 28.92,30.51 C39.+
BOOT_FLASH  (via drill 0.6)
  Top 0.254: 41.59,79.6 SW2.A 38.73,79.5 38.73,76.83 39.69,75.88 39.69,62.55 v37.47,60.33 | 41.59,79.6 SW2.A' | v33.02,60.33 32.55,59.85 IC4.60 | R14.2 41.59,77.57 41.59,79.6
  Bottom 0.254: v33.02,60.33 v37.47,60.33
GND  (via drill 0.6)
  other vias: 42.23,42.86 26.99,40.96 8.26,78.74 7.94,72.39 30.8,49.21 14.29,63.18 36.83,39.37 23.18,67.94 19.68,72.71 33.02,72.71 22.54,62.23 41.59,81.6 32.07,64.77 7.62,105.41 47.31,100.01 1.59,99.06 1.59,88.9 1.59,7.62 12.7,1.59 24.13,1.59 36.83,1.59 47.31,7.62 47.31,17.78 45.09,27.62 45.4,36.2 47.31,50.01 37.47,99.06 32.07,92.71 10.79,99.38 5.4,92.08 14.61,53.02 25.08,54.61 21.91,57.47 33.02,67.31 30.8,52.39 12.38,72.39 29.84,89.53 37.47,63.5 37.15,74.3 26.04,30.96 15.24,27.3 20.64,27.3 33.66,85.72 38.1,42.39 28.89,34.77 46.67,30.96 8.57,29.21 35.88,92.71 40.64,101.6 42.55,101.6 44.45,101.6 46.35,101.6 47.31,98.11 47.31,96.2 47.31,94.3 35.24,36.51 42.23,35.88 46.67,41.27 46.99,46.2 38.73,32.7
  pour Bottom: 0,106.68 0,0 48.9,0 48.9,106.68
  pour Top: 0,106.68 48.9,106.68 48.9,0 0,0
I2C_SCL  (via drill 0.6)
  Top 0.254: IC5.24 40.22,39.69 38.89,39.69 35.24,43.34 34.29,43.34 33.71,43.92 R24.1 31.81,43.92 29.53,46.2 24.45,46.2 | v22.23,55.88 21.27,55.88 21.25,55.85 IC4.29 | 24.45,46.2 23.18,47.47 23.18,48.9 v22.86,49.21 | 24.45,46.2
  Bottom 0.254: v22.23,55.88 22.54,55.56 22.54,54.29 22.23,53.98 22.23,49.85 v22.86,49.21
I2C_SDA  (via drill 0.6)
  Top 0.254: IC5.23 40.23,39.05 38.73,39.05 34.92,42.86 32.07,42.86 29.21,45.72 27.3,45.72 | v21.59,54.61 20.85,55.35 IC4.30 | v22.23,47.94 22.23,47.31 23.81,45.72 27.3,45.72 | R25.1 | 27.3,45.72 R25.1
  Bottom 0.254: 21.59,49.53 21.59,48.9 | v22.23,47.94 21.91,48.26 21.91,49.21 21.59,49.53 | 21.59,49.53 v21.59,54.61
I2S_LRCK
  Top 0.254: IC5.5 33.93,39.73 34.29,39.37 34.29,38.73 33.97,38.42 32.77,38.42 IC5.7 32.74,38.42 22.7,38.42 19.05,42.07 19.05,49.85 20.38,51.18 IC4.33
I2S_SCK  (via drill 0.6)
  Top 0.254: v20,49.53 20,49.85 20.88,50.73 IC4.34 | IC5.3 31.67,41.03 30.48,39.85 23.65,39.85 20.95,42.55 20.95,46.04 v21.27,46.35
  Bottom 0.254: v20,49.53 20,47.62 v21.27,46.35
I2S_SIN
  Top 0.254: 32.73,39.05 IC5.6 31.46,39.08 31.27,38.89 23.02,38.89 20.32,41.59 | IC4.35 21.38,49.95 20.95,49.53 20.95,48.9 19.68,47.62 19.68,42.23 20.32,41.59 | 20.32,41.59
I2S_SOUT
  Top 0.254: 32.7,40.32 IC5.4 31.81,40.38 30.8,39.37 23.34,39.37 20.32,42.39 20.32,47.31 21.59,48.58 21.59,49.37 21.88,49.66 IC4.36
IN_1
  Top 0.254: IC5.20 38.72,37.13 38.1,36.51 38.1,36.04 34.61,32.54 34.61,31.3 C37.+
IN_2
  Top 0.254: IC5.19 39.02,36.48 38.73,36.2 38.73,35.56 36.2,33.02 36.2,27.65 C43.+
JTCK  (via drill 0.6)
  Top 0.254: IC4.49 30.8,54.35 | 30.8,54.35 31.18,54.35 | JP1.4 42.86,58.1 42.55,58.1 v40.96,58.1 | v40.96,55.24 40.32,55.88 34.92,55.88 33.4,54.35 30.8,54.35
  Bottom 0.254: v40.96,55.24 40.96,55.88 41.27,56.2 41.27,57.78 v40.96,58.1
JTDI
  Top 0.254: IC4.50 30.88,54.85 32.95,54.85 34.61,56.52 41.59,56.52 42.55,56.52 42.86,56.52 43.81,55.56 JP1.8
JTDO
  Top 0.254: JP1.6 43.5,56.83 43.18,57.15 42.55,57.15 42.23,57.15 41.91,57.15 38.1,57.15 36.83,57.15 36.63,57.35 IC4.55
JTMS  (via drill 0.6)
  Top 0.254: JP1.2 42.55,59.37 v42.23,59.05 | v42.23,55.56 42.23,54.93 41.59,54.29 40.64,54.29 39.69,55.24 35.24,55.24 33.81,53.82 27.78,53.82 26.88,52.91 IC4.46
  Bottom 0.254: v42.23,55.56 42.23,56.2 41.91,56.52 41.91,58.1 41.91,58.74 v42.23,59.05
LED_B
  Top 0.254: R4.1 24.45,89.85 25.4,88.9 28.26,88.9 33.97,83.19 33.97,76.52 35.56,74.93 35.56,61.59 33.32,59.35 IC4.59
LED_CARRIER_G
  Top 0.254: R22.1 16.51,57.15 17.21,57.85 IC4.25
LED_CARRIER_R
  Top 0.254: R21.1 16.83,58.74 17.21,58.35 IC4.24
LED_G
  Top 0.254: R5.1 26.35,89.85 26.67,89.53 28.57,89.53 34.61,83.5 34.61,76.83 36.2,75.25 36.2,61.28 33.77,58.85 IC4.58
LED_R
  Top 0.254: R3.1 22.54,89.85 24.13,88.27 27.94,88.27 33.34,82.87 33.34,76.2 34.92,74.61 34.92,62.55 33.66,61.28 32.7,61.28 31.78,60.35 IC4.61
LEVEL_1_CV
  Top 0.254: R13.1 C8.2 13.23,78 13.02,77.79 IC3.8 13.02,74.93 13.34,74.61 14.92,74.61 16.19,73.34 16.19,69.53 16.19,68.26 16.19,67.63 18.73,65.09 20.32,65.09 20.64,65.09 20.88,64.84 IC4.15
LEVEL_1_POT
  Top 0.254: IC4.21 17.3,59.85 16.83,60.33 13.65,60.33 12.06,61.91 4.76,61.91 3.81,60.96 3.81,58.74 4.45,58.1 5.4,58.1 6.35,57.15 6.35,46.04 7.94,44.45 7.94,39.37 7.3,38.73 R26.P$2 7.3,34.61 6.03,33.34 5.5,33.34 C33.1
LEVEL_2_CV
  Top 0.254: R12.1 C7.2 5.18,78 5.4,77.79 IC3.14 5.4,74.93 6.35,73.98 13.34,73.98 14.61,73.98 15.56,73.03 15.56,69.53 15.56,69.22 15.56,67.94 15.56,67.31 18.41,64.45 19.68,64.45 20.1,64.04 IC4.16
LEVEL_2_POT
  Top 0.254: R27.P$2 20.32,36.51 19.05,37.78 15.56,37.78 | 15.56,37.78 10.16,37.78 8.57,39.37 8.57,44.77 6.99,46.35 6.99,57.47 5.71,58.74 4.6,58.74 4.29,59.05 4.29,60.48 5.08,61.28 11.75,61.28 13.34,59.69 16.51,59.69 16.85,59.35 IC4.22 | 15.56,37.78 C31.1
MOD_OUT
  Top 0.254: 32.7,35.24 IC5.12 31.69,35.18 30.96,34.45 30.96,33.66 30,32.7 C32.+
N$1
  Top 0.254: R9.2 13.34,82.02 13.34,82.55 13.02,82.87 4.45,82.87 3.49,81.92 3.49,77.15 3.49,65.72 1.27,63.5 | 1.27,63.18 1.27,46.67 5.08,42.86 5.08,41.27 1.27,37.47 1.27,20.32 5.08,16.51 J1.P3 | 1.27,63.18 1.27,63.5 | 1.27,63.18 1.27,63.5 | 1.27,63.18 1.27,63.5
N$2
  Top 0.254: R11.1 10.26,81.92 R9.1 R13.2 C8.1 11.53,78 11.75,77.79 IC3.9
N$3
  Top 0.254: LED2.3 10.48,59.69 11.75,59.69 12.7,58.74 R21.2
N$4
  Top 0.254: J2.P3 17.14,17.78 4.76,17.78 1.91,20.64 1.91,37.15 5.71,40.96 5.71,43.18 1.91,46.99 1.91,63.18 4.13,65.41 4.13,73.98 4.13,81.6 4.45,81.92 R8.2
N$5
  Top 0.254: R10.1 8.15,81.92 R8.1 R12.2 C7.1 6.88,78 6.67,77.79 IC3.13
N$6  (via drill 0.6)
  Top 0.254: v32.38,16.51 31.11,17.78 29.21,17.78 27.94,19.05 8.26,19.05 5.4,19.05 3.17,21.27 3.17,36.51 6.99,40.32 6.99,43.81 3.17,47.62 3.17,59.69 3.17,61.28 4.45,62.55 11.75,62.55 12.7,62.55 13.23,63.08 R18.2
  Bottom 0.254: v32.38,16.51 J4.P3
N$7
  Top 0.254: Q1.2 31.22,70.84 C11.2 | Q1.2 31.11,70.74 31.11,70.48 | IC4.5 25.88,67.16 27.62,68.9 30.48,68.9 30.8,69.22 31.18,69.6 Q1.2
N$8
  Top 0.254: IC4.6 25.38,67.33 23.81,68.9 22.23,68.9 21.53,69.6 Q1.1 21.49,70.84 C10.2
N$9
  Top 0.254: J1.P2 5.4,24.13 4.45,25.08 R32.2
N$10
  Top 0.254: R17.2 4.45,64.77 2.54,62.87 2.54,47.31 6.35,43.5 6.35,40.64 2.54,36.83 2.54,20.95 5.08,18.41 27.62,18.41 28.26,17.78 29.53,16.51 J3.P3
N$11
  Top 0.254: IC3.2 6.67,68.9 6.88,68.68 C12.1 R15.2 R17.1 6.88,63.92 7.3,63.5 8.15,63.5 R19.1
N$12
  Top 0.254: R35.2 10.16,26.57 10.16,25.08 11.11,24.13 J2.P2
N$13
  Top 0.254: C22.1 27.3,50.16 27.38,50.24 IC4.47
N$14
  Top 0.254: LED2.1 5.71,59.69 6.67,58.74 10.48,58.74 11.75,58.74 13.34,57.15 R22.2
N$15
  Top 0.254: R20.1 10.26,63.5 11.11,63.5 11.53,63.92 R18.1 R16.2 C14.1 11.53,68.68 11.75,68.9 IC3.6
N$16
  Top 0.406: IC1.2 40.86,104.78 34.61,104.78 33.66,103.82 33.66,101.6 C2.+ 32.84,103.68 31.75,104.78 18.1,104.78 17.46,104.14 R1.1
N$17
  Top 0.254: IC5.16 41.35,34.53 41.91,33.97 41.91,31.43 41.59,31.11 C36.+ 40.51,28.55 C42.1
N$18
  Top 0.254: C37.- 32.2,26.22 35.56,22.86 35.56,17.46 33.34,15.24 24.45,15.24 23.5,14.29 R37.1 R36.2 C44.1
N$19
  Top 0.254: C19.1 16.75,54.85 IC4.31
N$20
  Top 0.254: R38.2 25.08,6.35 20.64,1.91 J6.P3
N$21
  Top 0.254: R37.2 23.5,7.3 19.68,3.49 13.34,3.49 11.75,1.91 J5.P3
N$22
  Top 0.254: C43.- 33.62,25.75 36.2,23.18 36.2,17.14 33.66,14.61 25.72,14.61 25.08,13.97 R38.1 R39.2 C45.1
N$23
  Top 0.254: R33.2 R34.2 23.91,26.04 25.08,26.04 26.32,27.27 C39.-
N$24
  Top 0.254: TP3.P$1 39.37,58.42 38.8,57.85 IC4.56
N$25
  Top 0.254: R34.1 R31.2 C38.1 21.8,29.31 21.27,29.84 IC6.6
N$26
  Top 0.254: TP2.P$1 34.86,58.35 IC4.57
N$27
  Top 0.254: TP4.P$1 31.43,56.2 31.09,55.85 IC4.52
N$28  (via drill 0.6)
  Top 0.254: 38.42,12.17 R43.2 38.52,16.61 39.05,17.14 v39.05,18.41 | v34.29,18.41 32.38,18.41 31.75,19.05 29.84,19.05 24.77,24.13 21.27,24.13 19.68,25.72 19.68,27.3 19.05,27.94 18.73,27.94 18.41,28.26 18.41,30.8 18.73,31.11 IC6.7 20.16,31.01 C38.2 R31.1
  Bottom 0.254: v34.29,18.41 v39.05,18.41
N$29
  Top 0.254: J8.P3 42.55,2.86 40.22,5.18 R43.1
N$30
  Top 0.254: TP1.P$1 33.66,63.82 33.66,63.18 33.66,62.23 33.34,61.91 32.38,61.91 31.32,60.85 IC4.62
N$31
  Top 0.254: C32.- 26.99,32.7 26.04,33.66 22.86,33.66 22.54,33.34 9.84,33.34 9.53,33.02 R29.2 R28.2
N$32
  Top 0.254: R29.1 R30.2 C35.1 12.91,30.8 13.34,30.8 13.65,31.11 IC6.2
N$33  (via drill 0.6)
  Top 0.254: v33.34,17.46 32.38,17.46 31.43,18.41 29.53,18.41 24.45,23.5 20.95,23.5 19.05,25.4 17.78,25.4 17.14,26.04 17.14,27.3 17.78,27.94 17.78,30.8 16.19,32.38 IC6.1 12.8,32.38 C35.2 R30.1 | R42.2 34.61,12.17 34.61,14.29 v37.78,17.46
  Bottom 0.254: v33.34,17.46 v37.78,17.46
N$34
  Top 0.254: J7.P3 30.48,2.86 32.8,5.18 R42.1
N$35
  Top 0.254: R3.2 LED1.RED
N$36
  Top 0.254: R4.2 24.45,92.71 25.08,93.34 LED1.BLU
N$37
  Top 0.254: R5.2 LED1.GRN
N$38
  Top 0.254: J6.P2 17.14,9.53 16.41,10.26 R41.1
N$39
  Top 0.254: J5.P2 7.62,9.53 8.68,10.58 R40.1
N$40
  Top 0.254: C41.2 46.77,29.37 44.77,29.37 Q2.2 44.77,35.08 42.7,37.15 42.7,39.85 42.17,40.38 IC5.25
N$41
  Top 0.254: C26.2 46.73,42.7 44.77,42.7 Q2.1 44.77,37.47 44.45,37.15 43.81,37.15 43.18,37.78 43.18,40.48 42.63,41.03 IC5.26
N$42
  Top 0.406: D1.C 12.7,100.65 13.34,101.28 L1.2
N$43
  Top 0.406: D2.A 13.65,96.84 15.3,95.19 L3.2
N$56
  Top 0.406: JP3.2 JP3.1 | JP3.2 | D1.A 17.78,99.38 18.73,100.33 JP3.2
N$64
  Top 0.406: JP3.9 29.53,100.97 JP3.10 29.53,99.06 28.89,98.42 19.37,98.42 17.78,96.84 D2.C
NORMALIZATION_PROBE  (via drill 0.6)
  Top 0.254: 4.55,28.26 4.45,28.36 | 18.41,47.94 18.41,41.59 15.88,39.05 12.7,39.05 v12.38,39.37 | 18.41,47.94 18.41,50.01 19.84,51.44 19.84,53.18 20,53.34 23.18,53.34 23.38,53.14 IC4.39 | v12.38,34.29 12.06,33.97 9.53,33.97 8.89,33.34 6.99,33.34 6.35,32.7 6.35,28.26 | 6.35,28.26 4.55,28.26 | 6.35,28.26 7.62,28.26 8.36,27.52 R35.1 8.57,26.45 8.57,22.54 v10.79,20.32 | 14.61,12.17 R41.2 R40.2 10.38,16.09 v10.79,16.51 | D3.3 15.09,47.94 18.41,47.94 | 4.55,28.26 R32.1
  Bottom 0.254: v12.38,34.29 v12.38,39.37 | v10.79,16.51 v10.79,20.32
PARAMETER_CV
  Top 0.254: IC3.7 13.02,68.9 13.23,68.68 C14.2 R16.1 13.97,66.36 14.29,66.04 14.92,65.41 17.46,62.87 18.22,62.11 | 18.22,62.11 IC4.17 18.22,62.11
PARAMETER_POT  (via drill 0.6)
  Top 0.254: 37.78,46.67 R23.P$2 | v23.81,50.8 23.81,50.48 24.45,49.85 24.45,47.78 25.56,46.67 37.78,46.67 | v23.5,57.78 22.86,58.42 20,58.42 19.57,58.85 IC4.23 | C25.1 42.23,46.67 41.91,46.99 39.69,46.99 39.37,46.67 37.78,46.67
  Bottom 0.254: v23.81,50.8 23.81,57.47 v23.5,57.78
RESET  (via drill 0.6)
  Top 0.254: 38.73,86.04 SW1.B' 38.92,86.04 v43.18,86.04 | 44.45,53.34 44.45,51.75 43.02,50.32 34.45,50.32 32.23,48.1 26.51,48.1 26.04,48.58 26.04,50.48 v26.35,50.8 | 44.45,53.34 JP1.10 | 44.45,53.34 46.04,53.34 46.67,53.98 46.67,60.33 45.72,61.28 43.81,61.28 42.86,62.23 42.86,73.03 v42.23,73.66 | SW1.B 45.53,86.04 v43.18,86.04 | v26.35,61.59 24.88,63.07 IC4.7 | v43.18,86.04 43.18,91.44 42.55,92.08 R2.1
  Bottom 0.254: v26.35,50.8 v26.35,61.59 | v43.18,86.04 43.18,74.61 v42.23,73.66
RX
  Top 0.254: 25.4,52.24 IC4.43 25.38,48.44 26.19,47.62 32.54,47.62 34.61,49.69 43.18,49.69 47.31,53.82 | JP2.4 44.13,68.9 43.5,68.26 43.5,62.55 44.13,61.91 46.04,61.91 47.31,60.64 47.31,53.82 | 47.31,53.82
SW_CARRIER
  Top 0.254: IC4.27 17.48,56.85 17.3,56.67 17.3,56.36 16.83,55.88 11.11,55.88 10.4,56.59 SW3.4 SW3.3
TX
  Top 0.254: IC4.42 24.88,48.15 25.88,47.15 32.86,47.15 34.77,49.05 43.34,49.05 47.94,53.66 47.94,60.96 46.67,62.23 46.67,65.72 46.04,66.36 JP2.5
VCC  (via drill 0.6)
  Top 0.406: C34.1 IC6.8 v17.78,32.38 | v3.17,86.68 3.17,97.47 5.54,99.83 C1.+ 5.71,101.6 5.71,102.87 6.99,104.14 R1.2 13.18,103.02 13.65,102.55 14.92,102.55 15.56,101.92 15.56,101.33 L1.1
  Bottom 0.406: v3.17,86.68 2.54,86.04 2.54,46.67 5.71,43.5 5.71,40.64 3.17,38.1 3.17,34.61 5.4,32.38 v17.78,32.38
VEE  (via drill 0.6)
  Top 0.406: v1.59,85.09 3.49,85.09 5.08,86.68 5.08,87.63 | IC6.4 C40.2 12.6,27.73 v13.02,27.3 | L3.1 12.7,94.93 12.06,94.3 C3.- 9.53,94.3 9.53,93.34 5.08,88.9 5.08,87.63 | R6.1 7.09,87.63 5.08,87.63
  Bottom 0.406: v1.59,85.09 1.91,84.77 1.91,46.35 5.08,43.18 5.08,40.96 2.54,38.42 2.54,33.81 9.05,27.3 v13.02,27.3

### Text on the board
tNames: RESET | SYSBOOT | Warps | cc-by-sa | Émilie Gillet | 2015. v3
bNames: stripe | Red | +12V | GND | -12V | GND | <TX | JTAG | Warps | cc-by-sa Émilie Gillet, 2015. v3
